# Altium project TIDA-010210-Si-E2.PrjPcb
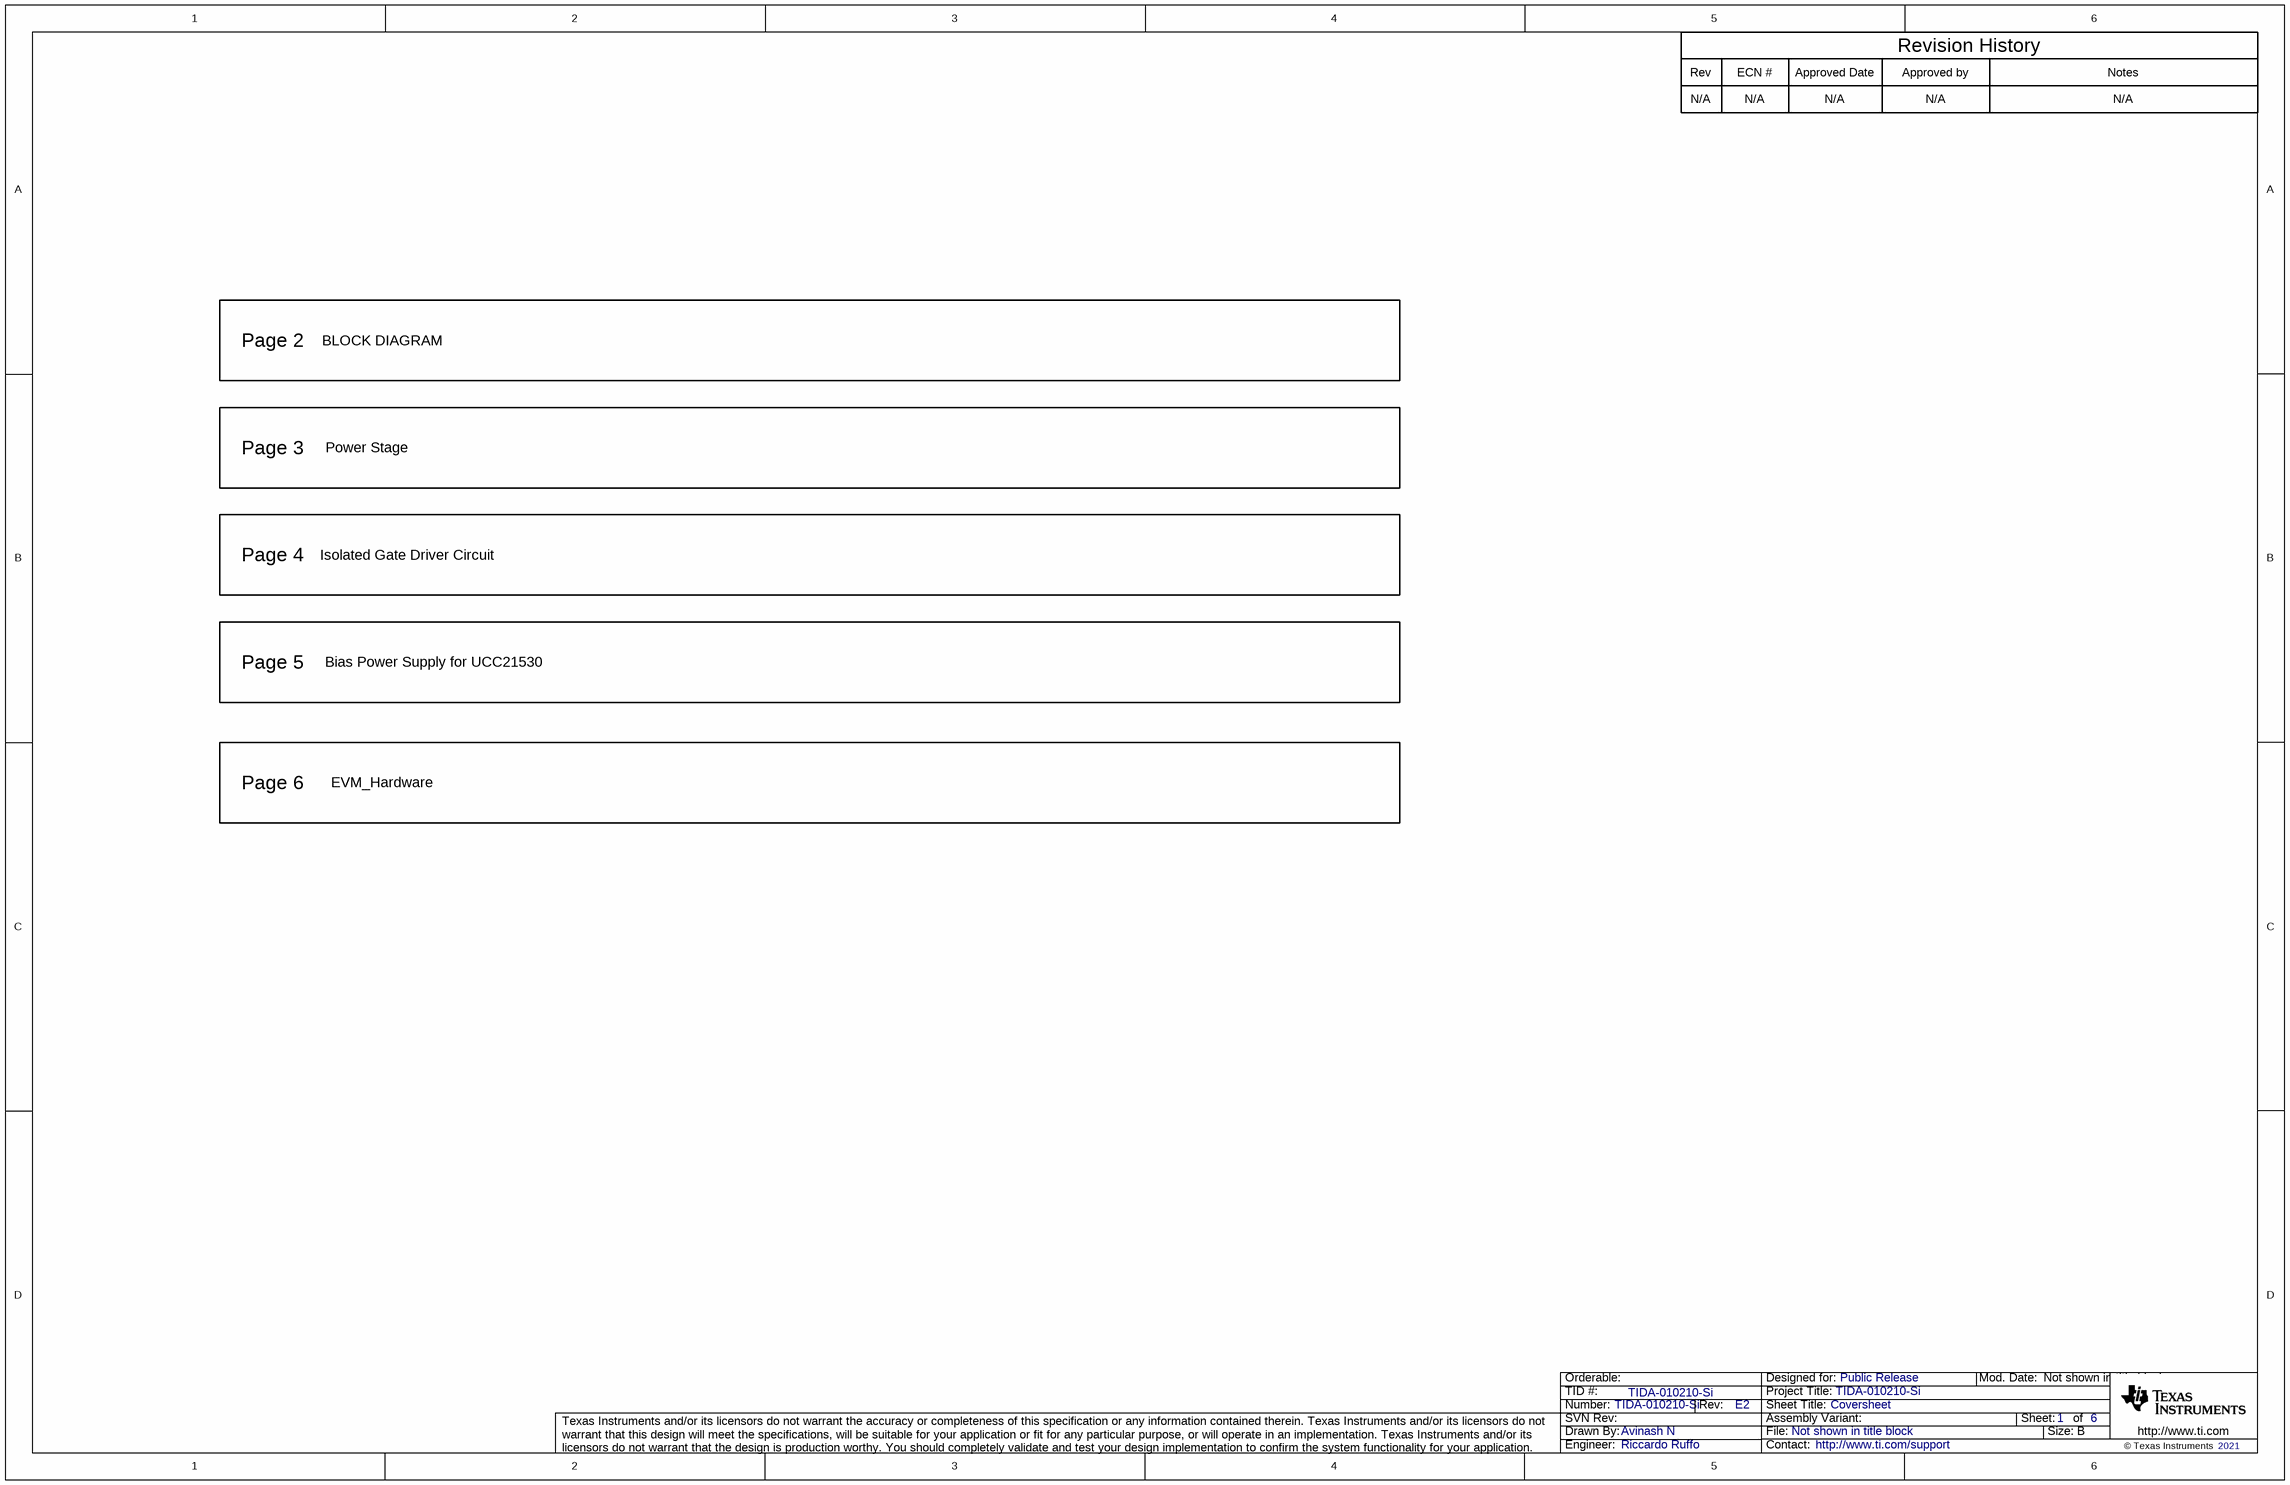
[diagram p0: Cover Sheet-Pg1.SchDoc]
TID: TIDA-010210-Si; TechSupport: http://www.ti.com/support; SCH_Rev: E2; PRJ_Title: TIDA-010210-Si; PRJ_Number: TIDA-010210-Si; PRJ_Engineer: Riccardo Ruffo; PRJ_Customer: Public Release; PCB_Rev: E2; PCB_Layout: Riccardo Ruffo; CopyrightYear: 2021
6 sheets, 79 parts. Net scope: flat (ports and power ports of the same name join across sheets).
Board file: TIDA-010210-Si-E2.PcbDoc
Sheets:
  Cover Sheet-Pg1.SchDoc
  Block Diagram-Pg2.SchDoc
  Power Stage-Pg3.SchDoc
  Gate Driver Circuit-Pg4.SchDoc
  Bias Power Supply-Pg5.SchDoc
  EVM Hardware-Pg6.SchDoc

## Sheet Cover Sheet-Pg1.SchDoc: Coversheet
size 431 x 279 mm; Date: Not shown in title block; ApprovedBy: Not shown in title block; CheckedBy: Not shown in title block; Author: Not shown in title block; CompanyName: Not shown in title block; DrawnBy: Avinash N; Engineer: Not shown in title block; Organization: Not shown in title block; Address1: Not shown in title block; Address2: Not shown in title block; Address3: Not shown in title block; Address4: Not shown in title block; DocumentNumber: 1; Revision: Use project parameter SCH_Rev; SheetNumber: 1; SheetTotal: 6; PageSetup: Record=PageOptions¦CenterHorizontal=True¦CenterVertical=True¦PrintScale=1.00¦XCorrection=1.00¦YCorrection=1.00¦PrintKind=0¦BorderSize=5000000¦LeftOffset=0¦BottomOffset=0¦Orientation=2¦PaperLength=1000¦PaperWidth=1000¦Scale=100¦PaperSource=15¦PrintQuality=600¦MediaType=1¦DitherType=10¦PaperKind=Letter¦PrintScaleMode=1

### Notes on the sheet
- Rev
- N/A
- ECN #
- Approved Date
- Approved by
- Revision History
- Notes
- Page 2
- BLOCK DIAGRAM
- Page 3
- Power Stage
- Page 4
- Isolated Gate Driver Circuit
- Page 5
- Bias Power Supply for UCC21530
- Page 6
- EVM_Hardware

## Sheet Block Diagram-Pg2.SchDoc: Block Diagram
size 431 x 279 mm; Date: Not shown in title block; ApprovedBy: Not shown in title block; CheckedBy: Not shown in title block; Author: Not shown in title block; CompanyName: Not shown in title block; DrawnBy: Avinash N; Organization: Not shown in title block; Address1: Not shown in title block; Address2: Not shown in title block; Address3: Not shown in title block; Address4: Not shown in title block; DocumentNumber: 1; Revision: Use project parameter SCH_Rev; SheetNumber: 2; SheetTotal: 6; PageSetup: Record=PageOptions¦CenterHorizontal=True¦CenterVertical=True¦PrintScale=1.00¦XCorrection=1.00¦YCorrection=1.00¦PrintKind=0¦BorderSize=5000000¦LeftOffset=0¦BottomOffset=0¦Orientation=2¦PaperLength=1000¦PaperWidth=1000¦Scale=100¦PaperSource=15¦PrintQuality=600¦MediaType=1¦DitherType=10¦PaperKind=Letter¦PrintScaleMode=1

## Sheet Power Stage-Pg3.SchDoc: Hardware
size 431 x 279 mm; Date: Not shown in title block; ApprovedBy: Not shown in title block; CheckedBy: Not shown in title block; Author: Not shown in title block; CompanyName: Not shown in title block; DrawnBy: Avinash N; Engineer: Not shown in title block; Organization: Not shown in title block; Address1: Not shown in title block; Address2: Not shown in title block; Address3: Not shown in title block; Address4: Not shown in title block; DocumentNumber: 1; Revision: Use project parameter SCH_Rev; SheetNumber: 3; SheetTotal: 6; PageSetup: Record=PageOptions¦CenterHorizontal=True¦CenterVertical=True¦PrintScale=1.00¦XCorrection=1.00¦YCorrection=1.00¦PrintKind=0¦BorderSize=5000000¦LeftOffset=0¦BottomOffset=0¦Orientation=2¦PaperLength=1000¦PaperWidth=1000¦Scale=100¦PaperSource=15¦PrintQuality=600¦MediaType=1¦DitherType=10¦PaperKind=Letter¦PrintScaleMode=1
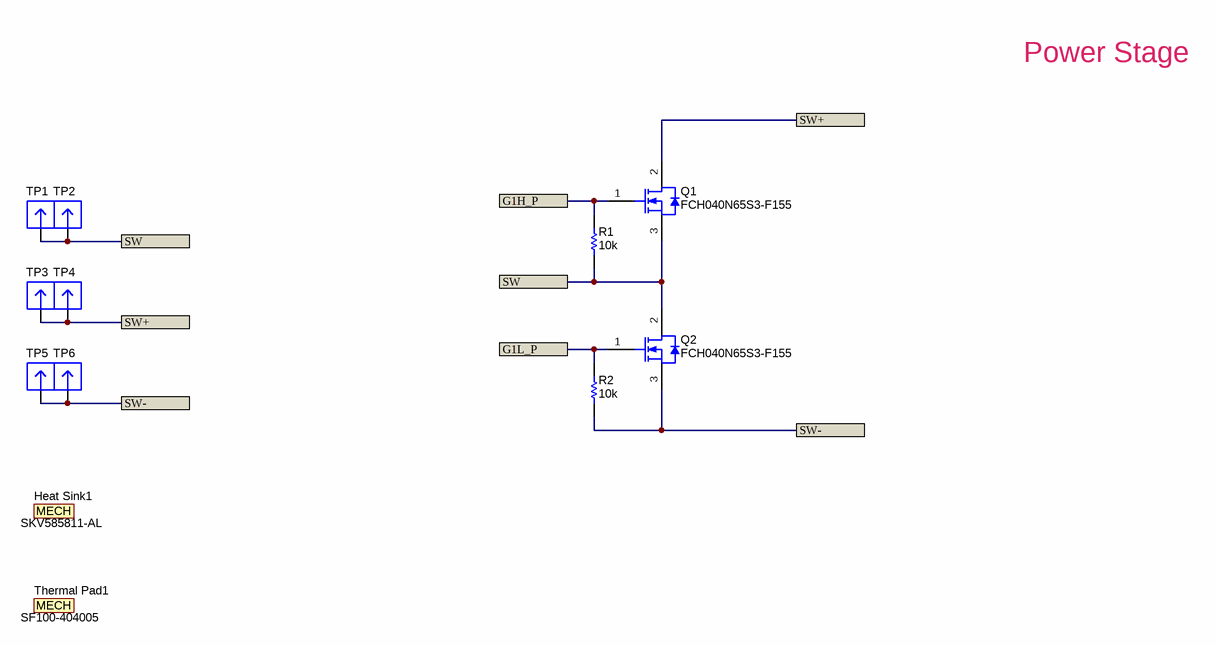
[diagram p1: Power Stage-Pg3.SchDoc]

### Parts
Heat_Sink1  SKV585811-AL  [SKV585811_AL]
Q1  FCH040N65S3-F155  [TO-247_Horizontal_Down]
Q2  FCH040N65S3-F155  [TO-247_Horizontal_Down]
R1  ValueDisplayed: 10k  [0603]  (hidden comment: CRCW060310K0JNEA)
R2  ValueDisplayed: 10k  [0603]  (hidden comment: CRCW060310K0JNEA)
Thermal_Pad1  SF100-404005  [SKV585811_AL]  (mechanical)
TP1  3620-2-32-15-00-00-08-0  [Mill-Max_3620-2-32-xx-00-00-08-0]  (value not drawn)
TP2  3620-2-32-15-00-00-08-0  [Mill-Max_3620-2-32-xx-00-00-08-0]  (value not drawn)
TP3  3620-2-32-15-00-00-08-0  [Mill-Max_3620-2-32-xx-00-00-08-0]  (value not drawn)
TP4  3620-2-32-15-00-00-08-0  [Mill-Max_3620-2-32-xx-00-00-08-0]  (value not drawn)
TP5  3620-2-32-15-00-00-08-0  [Mill-Max_3620-2-32-xx-00-00-08-0]  (value not drawn)
TP6  3620-2-32-15-00-00-08-0  [Mill-Max_3620-2-32-xx-00-00-08-0]  (value not drawn)

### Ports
G1H_P, G1L_P, SW, SW+, SW-

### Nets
G1H_P: Q1.1(G) R1.2 ; port G1H_P
G1L_P: Q2.1(G) R2.2 ; port G1L_P
SW: Q1.3(S) Q2.2(D) R1.1 TP1.1 TP2.1 ; port SW
SW+: Q1.2(D) TP3.1 TP4.1 ; port SW+
SW-: Q2.3(S) R2.1 TP5.1 TP6.1 ; port SW-

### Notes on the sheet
- Power Stage

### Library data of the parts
Heat_Sink1 = 3-101004U: ALUMINUM HEATSINK 57.9X59X11MM; Manufacturer: Wakefield-Vette
Q1 Q2 = IPW65R070C6FKSA1: MOSFET N-CH 650V 65A TO247-3; Manufacturer: ON Semiconductor; Alternate Manufacturer: None; U/M: EA; ChType: N; VdsMax_V: 650; Value1: ? ohm; Value2: 170 nC; QgTyp_nC: 170; Vgs_V: 20; IdsMax_A: 53.5; SizeAreaWB_mm2: 123.2; SizeArea_mm2: 78; SizeX_mm: 15.6; SizeY_mm: 5; SizeZ_mm: 25; AEC Category: Q101
R1 R2 = CMP-0025701-4: RES, 10 k, 5%, 0.1 W, AEC-Q200 Grade 0, 0603; Manufacturer: Vishay-Dale; Power_W: 100mW; TempCo: 200 ppm/C; Value_Code: 10k0; Value: 10k; EIA_Code: E24; SizeX_mm: 1.6; SizeY_mm: 0.8; SizeZ_mm: 1; Value2: 0.1W; SizeArea_mm2: 1.28; CompType: Resistor; AEC Qualified: Y; VDC_V: 75V; AEC Category: Q200; AEC Grade: 0
Thermal_Pad1 = 3-101004U: Thermal Pad Blue 40.00mm x 40.00mm Square Tacky - Both Sides; Manufacturer: CUI Devices; CompType: THERM PAD
TP1-TP6 = CMP-0055044-1: Manufacturer: Mill-Max; CNHeader: FALSE; Gender: Male; CompType: PCB Pin; Row_Count: 1; ContactFinish: Gold

## Sheet Gate Driver Circuit-Pg4.SchDoc: Hardware
size 431 x 279 mm; Date: Not shown in title block; ApprovedBy: Not shown in title block; CheckedBy: Not shown in title block; Author: Not shown in title block; CompanyName: Not shown in title block; DrawnBy: Avinash N; Engineer: Not shown in title block; Organization: Not shown in title block; Address1: Not shown in title block; Address2: Not shown in title block; Address3: Not shown in title block; Address4: Not shown in title block; DocumentNumber: 1; Revision: Use project parameter SCH_Rev; SheetNumber: 4; SheetTotal: 6; PageSetup: Record=PageOptions¦CenterHorizontal=True¦CenterVertical=True¦PrintScale=1.00¦XCorrection=1.00¦YCorrection=1.00¦PrintKind=0¦BorderSize=5000000¦LeftOffset=0¦BottomOffset=0¦Orientation=2¦PaperLength=1000¦PaperWidth=1000¦Scale=100¦PaperSource=15¦PrintQuality=600¦MediaType=1¦DitherType=10¦PaperKind=Letter¦PrintScaleMode=1
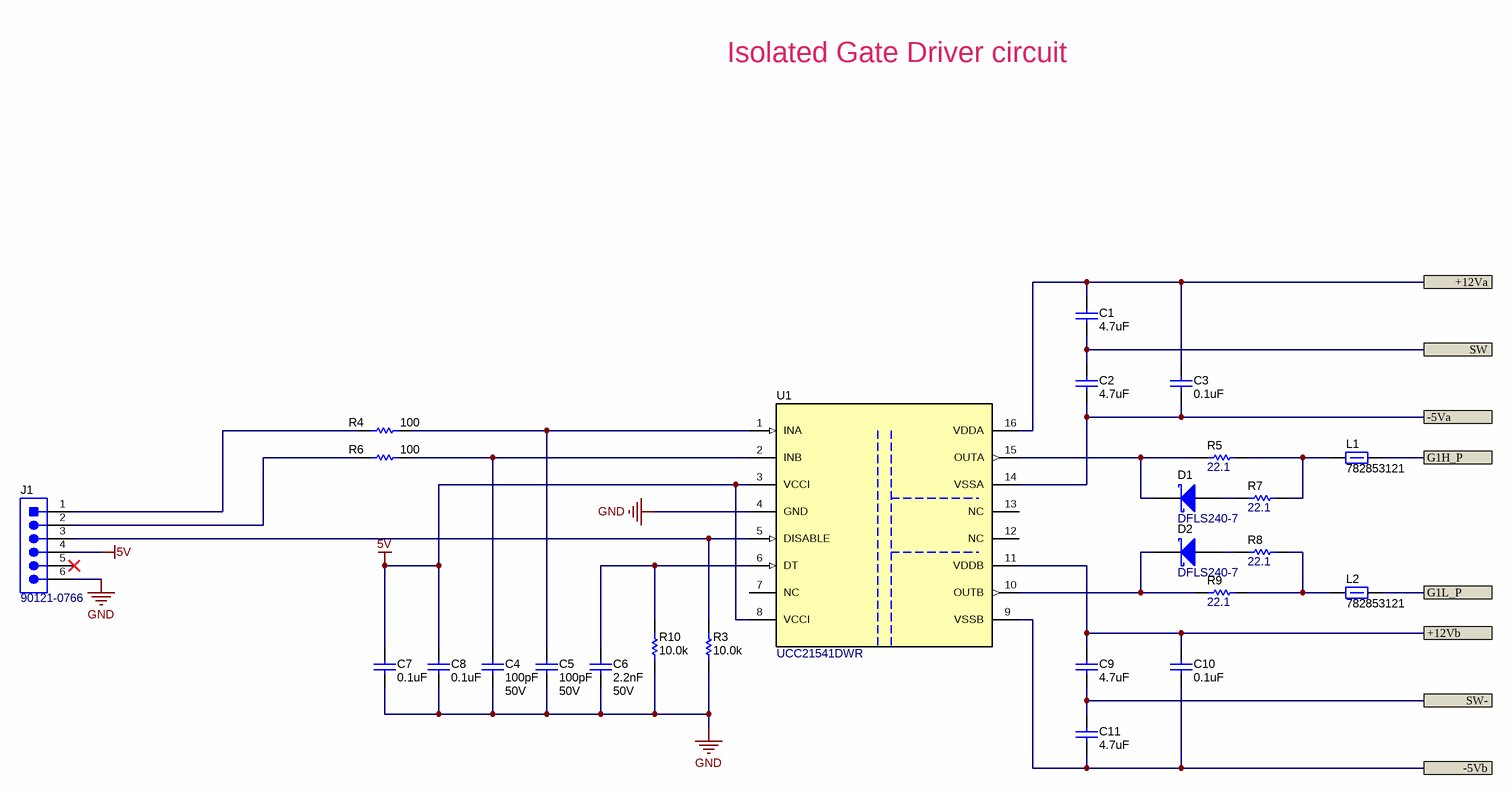
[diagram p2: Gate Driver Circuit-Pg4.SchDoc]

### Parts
C1  ValueDisplayed: 4.7uF  [0603]  (hidden comment: C1608X5R1V475K080AC)
C2  ValueDisplayed: 4.7uF  [0603]  (hidden comment: C1608X5R1V475K080AC)
C3  ValueDisplayed: 0.1uF  [0603]  (hidden comment: C1608X7R1H104K080AA)
C4  Cap_F: 100pF  VDC_V: 50V  [0603]  (hidden comment: CL10B101KB8NNNC)
C5  Cap_F: 100pF  VDC_V: 50V  [0603]  (hidden comment: CL10B101KB8NNNC)
C6  Cap_F: 2.2nF  VDC_V: 50V  [0603]  (hidden comment: C0603X222K5RACTU)
C7  ValueDisplayed: 0.1uF  [0603]  (hidden comment: C1608X7R1H104K080AA)
C8  ValueDisplayed: 0.1uF  [0603]  (hidden comment: C1608X7R1H104K080AA)
C9  ValueDisplayed: 4.7uF  [0603]  (hidden comment: C1608X5R1V475K080AC)
C10  ValueDisplayed: 0.1uF  [0603]  (hidden comment: C1608X7R1H104K080AA)
C11  ValueDisplayed: 4.7uF  [0603]  (hidden comment: C1608X5R1V475K080AC)
D1  DFLS240-7  [PowerDI123]
D2  DFLS240-7  [PowerDI123]
J1  90121-0766  [Molex_90121-0766]
L1  782853121  [0805_HV]
L2  782853121  [0805_HV]
R3  ValueDisplayed: 10.0k  [0603]  (hidden comment: RCA06031K00JNEA)
R4  ValueDisplayed: 100  [0603]  (hidden comment: CRCW0603100RFKEA)
R5  ValueDisplayed: 22.1  [0805_HV]  (hidden comment: CRCW080522R1FKEA)
R6  ValueDisplayed: 100  [0603]  (hidden comment: CRCW0603100RFKEA)
R7  ValueDisplayed: 22.1  [0805_HV]  (hidden comment: CRCW080522R1FKEA)
R8  ValueDisplayed: 22.1  [0805_HV]  (hidden comment: CRCW080522R1FKEA)
R9  ValueDisplayed: 22.1  [0805_HV]  (hidden comment: CRCW080522R1FKEA)
R10  ValueDisplayed: 10.0k  [0603]  (hidden comment: RT0603BRD0710KL)
U1  PartNumber: UCC21541DWR  [DW0016B_HV]  (hidden comment: UCC21540DWR)

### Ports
+12Va, +12Vb, -5Va, -5Vb, G1H_P, G1L_P, SW, SW-

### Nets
5V: C7.1 C8.1 J1.4 U1.3(VCCI) U1.8(VCCI)
GND: C4.2 C5.2 C6.2 C7.2 C8.2 J1.6 R3.1 R10.1 U1.4(GND)
+12Va: C1.1 C3.1 U1.16(VDDA) ; port +12Va
+12Vb: C9.1 C10.1 U1.11(VDDB) ; port +12Vb
-5Va: C2.1 C3.2 U1.14(VSSA) ; port -5Va
-5Vb: C10.2 C11.1 U1.9(VSSB) ; port -5Vb
G1H_P: L1.2 ; port G1H_P
G1L_P: L2.2 ; port G1L_P
SW: C1.2 C2.2 ; port SW
SW-: C9.2 C11.2 ; port SW-
NetC4_1: C4.1 R6.2 U1.2(INB)
NetC5_1: C5.1 R4.2 U1.1(INA)
NetC6_1: C6.1 R10.2 U1.6(DT)
NetD1_1: D1.1(K) R5.1 U1.15(OUTA)
NetD1_2: D1.2(A) R7.1
NetD2_1: D2.1(K) R9.1 U1.10(OUTB)
NetD2_2: D2.2(A) R8.1
NetJ1_1: J1.1 R4.1
NetJ1_2: J1.2 R6.1
NetJ1_3: J1.3 R3.2 U1.5(DISABLE)
NetL1_1: L1.1 R5.2 R7.2
NetL2_1: L2.1 R8.2 R9.2

Not connected (* = marked no-connect by the designer): J1 5*; U1 7(NC) 12(NC) 13(NC)

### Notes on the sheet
- Isolated Gate Driver circuit

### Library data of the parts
C1 C2 C9 C11 = CMP-0007022-5: CAP, CERM, 4.7 uF, 35 V, +/- 10%, X5R, 0603; Manufacturer: TDK; TaMin_C: -55°C; ESR_ohm: 3.728m; Polarized: N; SizeAreaWB_mm2: 4.68; Value1: 0.003728 ohm; U/M: EA; Value: 4.7uF; TaMax_C: 85°C; SizeZ_mm: 1; SizeX_mm: 1.6; SizeY_mm: 0.8; Value2: 35V; SizeArea_mm2: 1.28; CompType: Capacitor; Cap_F: 4.7µF; IRMS_A: 2.69359A; AEC Category: Q200
C3 C7 C8 C10 = CMP-0007044-5: CAP, CERM, 0.1 uF, 50 V, +/- 10%, X7R, 0603; Manufacturer: TDK; TaMin_C: -55°C; ESR_ohm: 0.0296; Polarized: N; SizeAreaWB_mm2: 4.68; Value1: 0.0296 ohm; U/M: EA; Value: 0.1uF; TaMax_C: 125°C; SizeZ_mm: 1; SizeX_mm: 1.6; SizeY_mm: 0.8; Value2: 50V; SizeArea_mm2: 1.28; CompType: Capacitor; Cap_F: 100nF; IRMS_A: 9.7199dA; AEC Category: Q200
C4 C5 = CMP-0083857-1: CAP, CERM, 100 pF, 50 V,+/- 10%, X7R, 0603; Manufacturer: Samsung Electro-Mechanics; TaMin_C: -55°C; Polarized: N; SizeAreaWB_mm2: 4.68; U/M: EA; Value: 100pF; TaMax_C: 125°C; SizeZ_mm: 1; SizeX_mm: 1.6; SizeY_mm: 0.8; SizeArea_mm2: 1.28; AEC Category: Q200
C6 = CMP-0006983-4: CAP, CERM, 2200 pF, 50 V, +/- 10%, X7R, 0603; Manufacturer: Kemet; TaMin_C: -55°C; Polarized: N; SizeAreaWB_mm2: 4.68; Value1: Unknown; U/M: EA; Value: 2200pF; TaMax_C: 125°C; SizeZ_mm: 1; SizeX_mm: 1.6; SizeY_mm: 0.8; SizeArea_mm2: 1.28; AEC Category: Q200
D1 D2 = CMP-0028850-2: Diode, Schottky, 40 V, 2 A, AEC-Q101, PowerDI123; Manufacturer: Diodes Inc.; SizeArea_mm2: 6.586; Value: 40V; Green_REACh: Incomplete; Value2: 0.5V; Green_Lifecycle: Not Set; SizeX_mm: 3.7; AEC Qualified: Y; SizeY_mm: 1.78; AEC Category: Q101; Io_A: 2A; TJmax_C: 125°C; SizeAreaWB_mm2: 13.066; SizeZ_mm: 0.98; Vf_V: 500mV
J1 = CMP-0055334-1: Header, 2.54mm, 6x1, Gold, R/A, TH; Manufacturer: Molex; CNHeader: TRUE; Current_A: 3A; Shrouded: N; Gender: Male; Voltage_V: 350V; Row_Count: 1; Pitch_mm: 2.54; CT: FALSE; Cert_UL: Y
L1 L2 = CMP-0003294-1: Ferrite Bead, 120 ohm @ 100 MHz, 2.5 A, 0805; Manufacturer: Wurth Elektronik; Ztyp@1GHz_Ohm: 114.591; ZTyp@100MHz_Ohm: 120; SizeAreaWB_mm2: 6.75; DCR_ohm: 0.035; Value1: 0.035 ohm; Value: 120 ohm; Imax_A: 2.5A; SizeZ_mm: 1.45; SizeX_mm: 2; SizeY_mm: 1.25; SizeArea_mm2: 2.5
R3 = CMP-0025946-3: RES, 1.0 k, 5%, 0.1 W, AEC-Q200 Grade 0, 0603; Manufacturer: Vishay-Dale; Power_W: 100mW; TempCo: 200 ppm/C; Value_Code: 1k00; U/M: EA; Value: 1.0k; EIA_Code: E24; Res_ohm: 1k; SizeX_mm: 1.6; SizeY_mm: 0.8; SizeZ_mm: 1; Value2: 0.1W; SizeArea_mm2: 1.28; CompType: Resistor; AEC Qualified: Y; VDC_V: 75V; AEC Grade: 0; AEC Category: Q200
R4 R6 = CRCW0603100RFKEA: RES, 100, 1%, 0.1 W, 0603; Manufacturer: Vishay-Dale; CompType: Resistor; Value: 100; Value_Code: 100R; Tolerance_%: 1; Power_W: 0.1; Value2: 0.1W; VDC_V: 75; TempCo: 100 ppm/C; SizeArea_mm2: 1.28; SizeX_mm: 1.6; SizeY_mm: 0.8; EIA_Code: E96; U/M: EA; AEC Category: Q200; Green_Lifecycle: Active; Green_REACh: Passed
R5 R7-R9 = CMP-0021060-3: RES, 22.1, 1%, 0.125 W, AEC-Q200 Grade 0, 0805; Manufacturer: Vishay-Dale; Power_W: 125mW; TempCo: 100 ppm/C; Value_Code: 22R1; Value: 22.1; EIA_Code: E96; SizeX_mm: 2; SizeY_mm: 1.25; SizeZ_mm: 1.45; Value2: 0.125W; SizeArea_mm2: 2.5; AEC Qualified: Y; VDC_V: 150V; AEC Category: Q200; AEC Grade: 0
R10 = CMP-0023653-3: RES, 10.0 k, 0.1%, 0.1 W, 0603; Manufacturer: Yageo America; Power_W: 100mW; TempCo: 25 ppm/C; Value_Code: 10k0; U/M: EA; Value: 10.0k; EIA_Code: E192; Res_ohm: 10k; SizeX_mm: 1.6; SizeY_mm: 0.8; SizeZ_mm: 1; Value2: 0.1W; SizeArea_mm2: 1.28; CompType: Resistor; VDC_V: 75V; AEC Category: Q200
U1 = CMP-0083795-2: Isolated Dual-Channel Gate Driver, DW0016B (SOIC-16); Alternate Manufacturer: Texas Instruments; AEC Qualified: N; SizeZ_mm: 2.65; SizeX_mm: 10.4; SizeArea_mm2: 107.12; SizeY_mm: 10.3; AEC Category: Q200; SizeAreaWB_mm2: 152.52; CompType: IC

## Sheet Bias Power Supply-Pg5.SchDoc: Hardware
size 431 x 279 mm; Date: Not shown in title block; ApprovedBy: Not shown in title block; CheckedBy: Not shown in title block; Author: Not shown in title block; CompanyName: Not shown in title block; DrawnBy: Avinash N; Engineer: Not shown in title block; Organization: Not shown in title block; Address1: Not shown in title block; Address2: Not shown in title block; Address3: Not shown in title block; Address4: Not shown in title block; DocumentNumber: 1; Revision: Use project parameter SCH_Rev; SheetNumber: 5; SheetTotal: 6; PageSetup: Record=PageOptions¦CenterHorizontal=True¦CenterVertical=True¦PrintScale=1.00¦XCorrection=1.00¦YCorrection=1.00¦PrintKind=0¦BorderSize=5000000¦LeftOffset=0¦BottomOffset=0¦Orientation=2¦PaperLength=1000¦PaperWidth=1000¦Scale=100¦PaperSource=15¦PrintQuality=600¦MediaType=1¦DitherType=10¦PaperKind=Letter¦PrintScaleMode=1
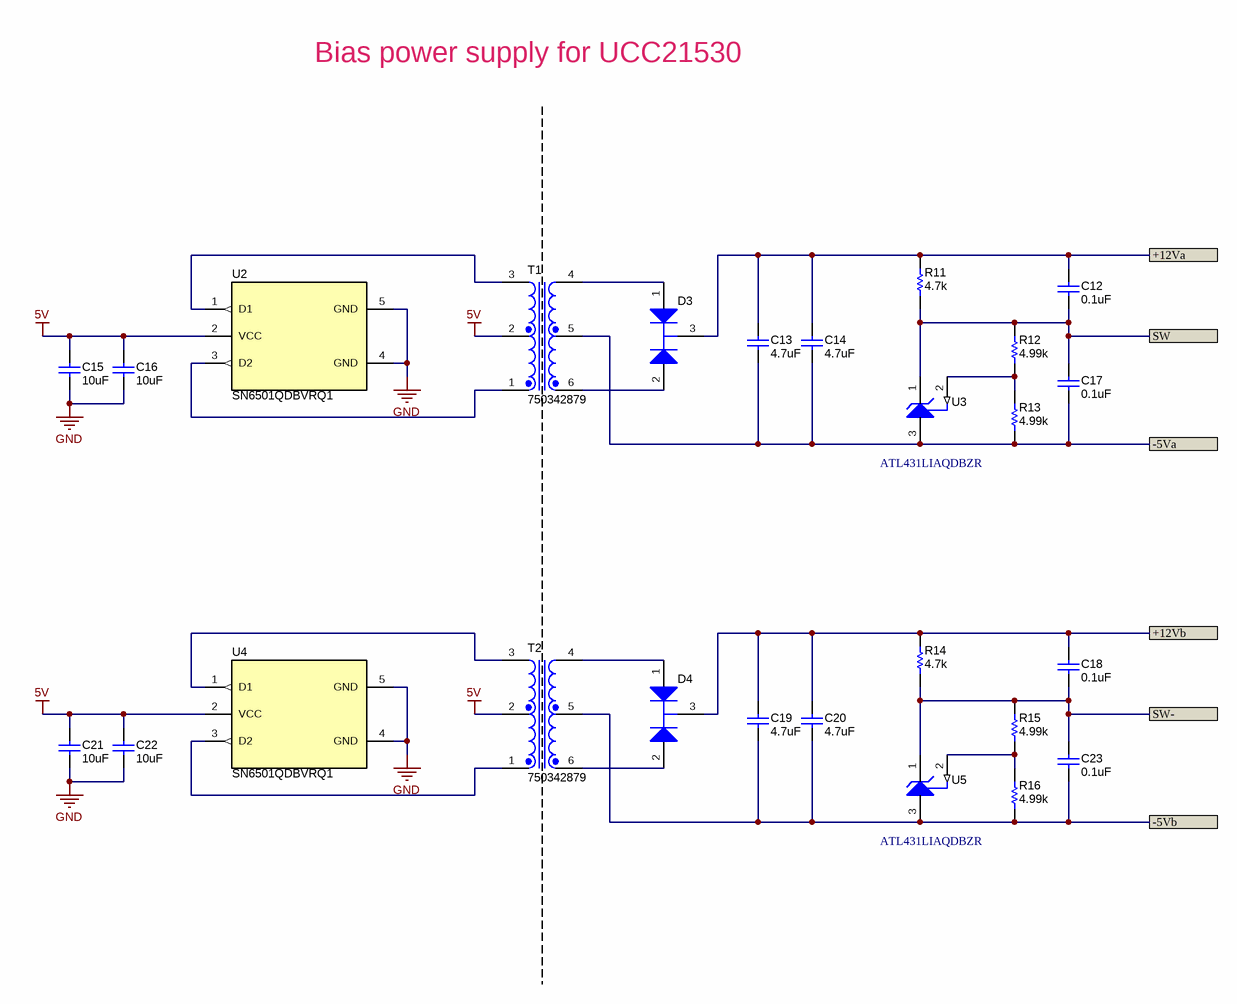
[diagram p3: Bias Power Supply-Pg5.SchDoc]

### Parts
C12  ValueDisplayed: 0.1uF  [0603]  (hidden comment: C1608X7R1H104K080AA)
C13  ValueDisplayed: 4.7uF  [0603]  (hidden comment: C1608X5R1V475K080AC)
C14  ValueDisplayed: 4.7uF  [0603]  (hidden comment: C1608X5R1V475K080AC)
C15  ValueDisplayed: 10uF  [0603]  (hidden comment: GRM188Z71A106MA73D)
C16  ValueDisplayed: 10uF  [0603]  (hidden comment: GRM188Z71A106MA73D)
C17  ValueDisplayed: 0.1uF  [0603]  (hidden comment: C1608X7R1H104K080AA)
C18  ValueDisplayed: 0.1uF  [0603]  (hidden comment: C1608X7R1H104K080AA)
C19  ValueDisplayed: 4.7uF  [0603]  (hidden comment: C1608X5R1V475K080AC)
C20  ValueDisplayed: 4.7uF  [0603]  (hidden comment: C1608X5R1V475K080AC)
C21  ValueDisplayed: 10uF  [0603]  (hidden comment: GRM188Z71A106MA73D)
C22  ValueDisplayed: 10uF  [0603]  (hidden comment: GRM188Z71A106MA73D)
C23  ValueDisplayed: 0.1uF  [0603]  (hidden comment: C1608X7R1H104K080AA)
D3  BAV70-E3-08  [SOT-23L]  (value not drawn)
D4  BAV70-E3-08  [SOT-23L]  (value not drawn)
R11  ValueDisplayed: 4.7k  [0805_HV]  (hidden comment: CRCW08054K70JNEA)
R12  ValueDisplayed: 4.99k  [0603]  (hidden comment: RT0603DRE074K99L)
R13  ValueDisplayed: 4.99k  [0603]  (hidden comment: RT0603DRE074K99L)
R14  ValueDisplayed: 4.7k  [0805_HV]  (hidden comment: CRCW08054K70JNEA)
R15  ValueDisplayed: 4.99k  [0603]  (hidden comment: RT0603DRE074K99L)
R16  ValueDisplayed: 4.99k  [0603]  (hidden comment: RT0603DRE074K99L)
T1  750342879  [Wurth_750342879]
T2  750342879  [Wurth_750342879]
U2  SN6501QDBVRQ1  [DBV0005A_L]
U3  ATL431LIAQDBZR  [DBZ0003A_N]
U4  SN6501QDBVRQ1  [DBV0005A_L]
U5  ATL431LIAQDBZR  [DBZ0003A_N]

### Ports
+12Va, +12Vb, -5Va, -5Vb, SW, SW-

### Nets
5V: C15.1 C16.1 C21.1 C22.1 T1.2 T2.2 U2.2(VCC) U4.2(VCC)
GND: C15.2 C16.2 C21.2 C22.2 U2.4(GND) U2.5(GND) U4.4(GND) U4.5(GND)
+12Va: C12.1 C13.1 C14.1 D3.3(C) R11.2 ; port +12Va
+12Vb: C18.1 C19.1 C20.1 D4.3(C) R14.2 ; port +12Vb
-5Va: C13.2 C14.2 C17.2 R13.1 T1.5 U3.3(ANODE) ; port -5Va
-5Vb: C19.2 C20.2 C23.2 R16.1 T2.5 U5.3(ANODE) ; port -5Vb
SW: C12.2 C17.1 R11.1 R12.2 U3.1(CATHODE) ; port SW
SW-: C18.2 C23.1 R14.1 R15.2 U5.1(CATHODE) ; port SW-
NetD3_1: D3.1(A) T1.4
NetD3_2: D3.2(K) T1.6
NetD4_1: D4.1(A) T2.4
NetD4_2: D4.2(K) T2.6
NetR12_1: R12.1 R13.2 U3.2(REF)
NetR15_1: R15.1 R16.2 U5.2(REF)
NetT1_1: T1.1 U2.3(D2)
NetT1_3: T1.3 U2.1(D1)
NetT2_1: T2.1 U4.3(D2)
NetT2_3: T2.3 U4.1(D1)

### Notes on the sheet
- Bias power supply for UCC21530

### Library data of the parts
C12 C17 C18 C23 = CMP-0007044-5: as C3 on sheet Gate Driver Circuit-Pg4
C13 C14 C19 C20 = CMP-0007022-5: as C1 on sheet Gate Driver Circuit-Pg4
C15 C16 C21 C22 = CMP-0007497-5: CAP, CERM, 10 uF, 10 V, +/- 20%, X7R, 0603; Manufacturer: MuRata; TaMin_C: -55°C; Polarized: N; SizeAreaWB_mm2: 4.68; Value1: Unknown; U/M: EA; Value: 10uF; TaMax_C: 125°C; SizeZ_mm: 1; SizeX_mm: 1.6; SizeY_mm: 0.8; Value2: 10V; SizeArea_mm2: 1.28; CompType: Capacitor; Cap_F: 10µF; AEC Category: Q200
D3 D4 = CMP-0077061-2: Diode, Switching, 70 V, 0.25 A, AEC-Q101, SOT-23; Manufacturer: Vishay-Semiconductor; SizeZ_mm: 1.1; AEC Qualified: Y; Value: 70V; SizeY_mm: 3.0; Value2: 1.25V; SizeArea_mm2: 7.5; AEC Category: Q101; SizeAreaWB_mm2: 14.0; Value1: 0.25A; Io_A: 2.5dA; SizeX_mm: 2.5; Green_REACh: Incomplete; TJmax_C: 150°C; Green_Lifecycle: Not Set
R11 R14 = CMP-0020559-3: RES, 4.7 k, 5%, 0.125 W, AEC-Q200 Grade 0, 0805; Manufacturer: Vishay-Dale; Power_W: 125mW; TempCo: 200 ppm/C; Value_Code: 4k70; Value: 4.7k; EIA_Code: E24; SizeX_mm: 2; SizeY_mm: 1.25; SizeZ_mm: 1.45; Value2: 0.125W; SizeArea_mm2: 2.5; CompType: Resistor; AEC Qualified: Y; VDC_V: 150V; AEC Category: Q200; AEC Grade: 0
R12 R13 R15 R16 = CMP-0025353-3: RES, 4.99 k, 0.5%, 0.1 W, 0603; Manufacturer: Yageo America; Power_W: 100mW; TempCo: 50 ppm/C; Value_Code: 4k99; U/M: EA; Value: 4.99k; EIA_Code: E192; SizeX_mm: 1.6; SizeY_mm: 0.8; SizeZ_mm: 1; Value2: 0.1W; SizeArea_mm2: 1.28; CompType: Resistor; VDC_V: 75V; AEC Category: Q200
T1 T2 = CMP-0030690-1: Transformer, 50 uH, SMT; Manufacturer: Wurth Elektronik; Value: 50uH; Ind_H: 50µH; Lp: 50
U2 U4 = CMP-0076093-1: Automotive Low-Noise 350 mA, 410 kHz Transformer Driver, DBV0005A (SOT-23-5); Manufacturer: Texas Instruments; SizeAreaWB_mm2: 14.82; SizeArea_mm2: 8.12; SizeZ_mm: 1.45; SizeY_mm: 2.9; U/M: EA; CompType: IC; SizeX_mm: 2.8
U3 U5 = CMP-0084733-1: High Bandwidth Low-Iq Programmable Shunt Regulator, DBZ0003A (SOT-23-3); Alternate Manufacturer: Texas Instruments; CompType: IC; SizeX_mm: 2.5; AEC Qualified: N; SizeZ_mm: 1.12; AEC Category: Q200; SizeY_mm: 3; SizeAreaWB_mm2: 14; SizeArea_mm2: 7.5

## Sheet EVM Hardware-Pg6.SchDoc: Hardware
size 431 x 279 mm; Date: Not shown in title block; ApprovedBy: Not shown in title block; CheckedBy: Not shown in title block; Author: Not shown in title block; CompanyName: Not shown in title block; DrawnBy: Avinash N; Engineer: Not shown in title block; Organization: Not shown in title block; Address1: Not shown in title block; Address2: Not shown in title block; Address3: Not shown in title block; Address4: Not shown in title block; DocumentNumber: 1; Revision: Use project parameter SCH_Rev; SheetNumber: 6; SheetTotal: 6; PageSetup: Record=PageOptions¦CenterHorizontal=True¦CenterVertical=True¦PrintScale=1.00¦XCorrection=1.00¦YCorrection=1.00¦PrintKind=0¦BorderSize=5000000¦LeftOffset=0¦BottomOffset=0¦Orientation=2¦PaperLength=1000¦PaperWidth=1000¦Scale=100¦PaperSource=15¦PrintQuality=600¦MediaType=1¦DitherType=10¦PaperKind=Letter¦PrintScaleMode=1
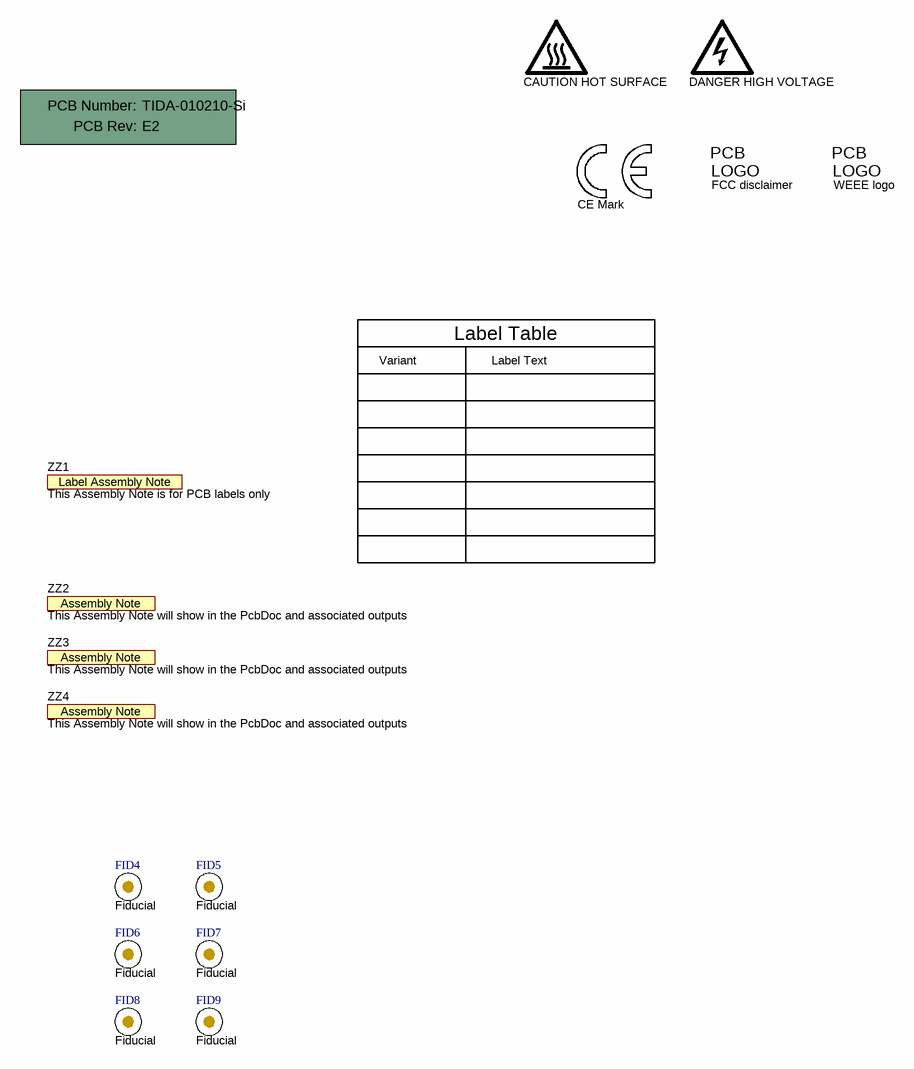
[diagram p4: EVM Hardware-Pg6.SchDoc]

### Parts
!PCB1  Printed Circuit Board  (value not drawn)  (mechanical)
FID4  Fiducial  [Fiducial10-30]
FID5  Fiducial  [Fiducial10-30]
FID6  Fiducial  [Fiducial10-30]
FID7  Fiducial  [Fiducial10-30]
FID8  Fiducial  [Fiducial10-30]
FID9  Fiducial  [Fiducial10-30]
LOGO1  CAUTION HOT SURFACE  [IEC_HotSurface_Small]  (no BOM)
LOGO2  DANGER HIGH VOLTAGE  [IEC_HighVoltage_Small]  (no BOM)
Logo4  CE Mark  [CE_Mark_5mm]  (no BOM)
Logo5  FCC disclaimer  [FCC_disclaimer_stacked]  (no BOM)
Logo6  WEEE logo  [WEEE_Minimum]  (no BOM)
ZZ1  This Assembly Note is for PCB labels only  [AssemblyNoteLabel]  (no BOM)
ZZ2  This Assembly Note will show in the PcbDoc and associated outputs  [AssemblyNote]  (no BOM)
ZZ3  This Assembly Note will show in the PcbDoc and associated outputs  [AssemblyNote]  (no BOM)
ZZ4  This Assembly Note will show in the PcbDoc and associated outputs  [AssemblyNote]  (no BOM)

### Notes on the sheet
- Variant
- Label Table
- Label Text

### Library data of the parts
!PCB1 = PCB: Manufacturer: Any; PartNumber: TIDA-010210-Si; SymbolCreator: a0412235
FID4-FID9 = CMP-0077181-1: Fiducial mark.  There is nothing to buy or mount.
LOGO1 = CMP-0074837-1: IEC 61010-1 Hot Surface Warning; SymbolCreator: a0412235; Lib Reference: IEC_HotSurface
LOGO2 = CMP-0074835-1: IEC 61010-1 High Voltage Warning; SymbolCreator: a0412235; Lib Reference: IEC_HighVoltage
Logo4 = CMP-0074844-1: SymbolCreator: a0412235
Logo5 = CMP-0074847-1: FCC_disclaimer; Library Reference: Logo
Logo6 = CMP-0074769-1
ZZ1 = AssemblyNoteLabel: SymbolCreator: a0412235
ZZ2-ZZ4 = AssemblyNote: SymbolCreator: codlsc

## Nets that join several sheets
5V: Gate Driver Circuit-Pg4 (5 pins), Bias Power Supply-Pg5 (8 pins)
GND: Gate Driver Circuit-Pg4 (9 pins), Bias Power Supply-Pg5 (8 pins)
+12Va: Gate Driver Circuit-Pg4 (C1.1 C3.1 U1.16), Bias Power Supply-Pg5 (5 pins)
+12Vb: Gate Driver Circuit-Pg4 (C9.1 C10.1 U1.11), Bias Power Supply-Pg5 (5 pins)
-5Va: Gate Driver Circuit-Pg4 (C2.1 C3.2 U1.14), Bias Power Supply-Pg5 (6 pins)
-5Vb: Gate Driver Circuit-Pg4 (C10.2 C11.1 U1.9), Bias Power Supply-Pg5 (6 pins)
G1H_P: Power Stage-Pg3 (Q1.1 R1.2), Gate Driver Circuit-Pg4 (L1.2)
G1L_P: Power Stage-Pg3 (Q2.1 R2.2), Gate Driver Circuit-Pg4 (L2.2)
SW: Power Stage-Pg3 (5 pins), Gate Driver Circuit-Pg4 (C1.2 C2.2), Bias Power Supply-Pg5 (5 pins)
SW-: Power Stage-Pg3 (Q2.3 R2.1 TP5.1 TP6.1), Gate Driver Circuit-Pg4 (C9.2 C11.2), Bias Power Supply-Pg5 (5 pins)

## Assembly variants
001: all parts fitted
